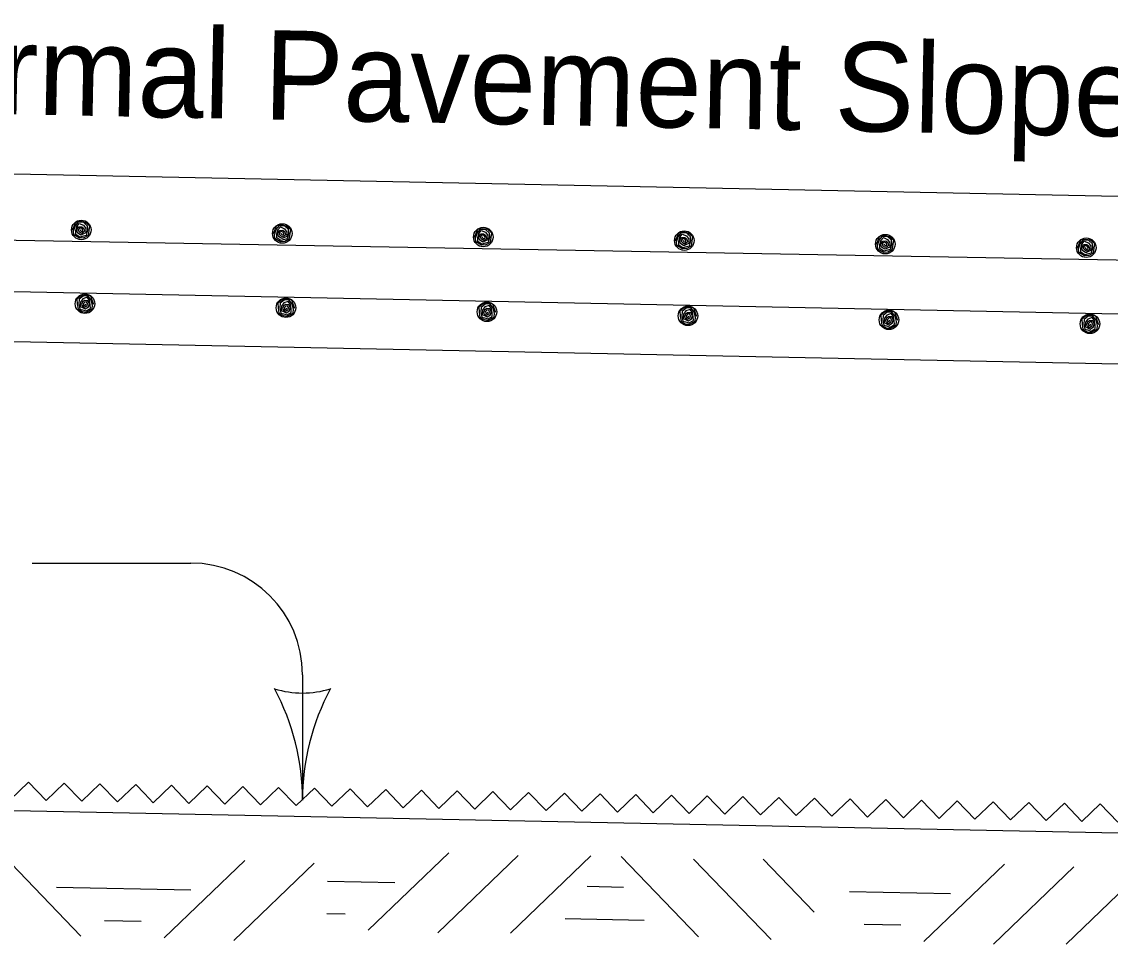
# Model space of a CAD drawing. Extents: x 10133 to 81668, y 7924 to 11018.
# Drawn here: x 10637.4 to 10832.4, y 8280 to 8445.3 of the extents above; entities that cross this region are included whole.
import ezdxf

# ---------------------------------------------------------------- set-up
doc = ezdxf.new("R2010")
doc.units = 0
doc.layers.add('BridgeExistingStructure', color=7, linetype='Continuous')
doc.layers.add('RasterAttachment', color=7, linetype='Continuous')

msp = doc.modelspace()

# ---------------------------------------------------------------- linework, layer by layer
at = {"layer": 'RasterAttachment'}
for p, q in [((10451.65, 8421.69), (11221.33, 8406.24)), ((10468, 8409.1), (11224.07, 8395.72)), ((10648.09, 8407.89), (10648.09, 8407.89)), ((10683.12, 8405.29), (10683.12, 8405.29)), ((10756.1, 8405.98), (10756.1, 8405.98)), ((10792.1, 8405.34), (10792.1, 8405.34)), ((10719.12, 8404.65), (10719.12, 8404.65)), ((10828.11, 8404.71), (10828.11, 8404.71)), ((11224.78, 8385.06), (10468.75, 8400.23)), ((10648.75, 8396.5), (10648.75, 8396.5)), ((10756.76, 8394.33), (10756.76, 8394.33)), ((10792.76, 8393.61), (10792.76, 8393.61)), ((10451.65, 8391.68), (11243.49, 8375.79)), ((10828.76, 8392.89), (10828.76, 8392.89)), ((10639.3, 8348.3), (10667.72, 8348.3)), ((10687.72, 8328.3), (10687.72, 8305.81)), ((10335.32, 8310), (11315.49, 8290.32)), ((10634.17, 8295.9), (10648.02, 8281.48)), ((10713.92, 8296.39), (10699.5, 8282.54)), ((10726.36, 8295.92), (10711.94, 8282.06)), ((10739.37, 8295.88), (10724.95, 8282.03)), ((10744.78, 8295.77), (10758.64, 8281.35)), ((10677.38, 8295.03), (10662.96, 8281.18)), ((10689.83, 8294.56), (10675.4, 8280.7)), ((10757.78, 8295.29), (10771.64, 8280.86)), ((10770.24, 8295.26), (10779.34, 8285.79)), ((10813.45, 8294.39), (10799.03, 8280.54)), ((10825.9, 8293.92), (10811.47, 8280.06)), ((10838.9, 8293.88), (10824.48, 8280.03))]:
    msp.add_line(p, q, dxfattribs=at)
for points in [[(10646.48, 8407.9), (10646.77, 8408.48), (10647.09, 8409.39), (10648.03, 8409.53), (10648.84, 8409.37), (10649.58, 8408.75), (10649.47, 8407.88), (10649.3, 8406.97), (10648.55, 8406.55), (10647.77, 8406.5), (10646.78, 8407.08), (10646.72, 8407.76), (10646.99, 8408.67), (10647.61, 8409.4), (10648.48, 8409.34), (10649.16, 8408.73), (10649.21, 8407.9), (10648.99, 8406.99), (10648.47, 8406.87), (10647.84, 8406.7), (10647.1, 8407.17), (10647.14, 8407.83), (10647.3, 8408.6), (10647.74, 8409.13), (10648.5, 8408.83), (10648.92, 8408.23), (10648.92, 8407.46), (10648.5, 8407.28), (10648.02, 8407.05), (10647.43, 8407.45), (10647.31, 8408.03), (10647.6, 8408.53), (10648.17, 8408.54), (10648.56, 8408.25), (10648.68, 8407.73), (10648.46, 8407.49), (10648.14, 8407.35), (10647.7, 8407.64), (10647.62, 8408.01), (10647.85, 8408.35), (10648.15, 8408.28), (10648.34, 8408.01), (10648.32, 8407.65), (10648.06, 8407.67), (10647.93, 8407.99)], [(10682.49, 8407.26), (10682.77, 8407.84), (10683.09, 8408.75), (10684.03, 8408.89), (10684.84, 8408.73), (10685.58, 8408.12), (10685.47, 8407.25), (10685.3, 8406.33), (10684.55, 8405.92), (10683.78, 8405.86), (10682.79, 8406.45), (10682.73, 8407.12), (10682.99, 8408.03), (10683.61, 8408.76), (10684.48, 8408.71), (10685.16, 8408.09), (10685.21, 8407.26), (10685, 8406.35), (10684.47, 8406.23), (10683.84, 8406.07), (10683.1, 8406.53), (10683.14, 8407.2), (10683.3, 8407.96), (10683.75, 8408.5), (10684.5, 8408.19), (10684.92, 8407.59), (10684.92, 8406.82), (10684.5, 8406.64), (10684.02, 8406.41), (10683.43, 8406.82), (10683.31, 8407.39), (10683.6, 8407.89), (10684.17, 8407.9), (10684.56, 8407.62), (10684.68, 8407.09), (10684.46, 8406.85), (10684.14, 8406.72), (10683.7, 8407), (10683.62, 8407.37), (10683.85, 8407.72), (10684.15, 8407.64), (10684.34, 8407.38), (10684.32, 8407.01), (10684.06, 8407.03), (10683.93, 8407.35)], [(10718.49, 8406.62), (10718.78, 8407.2), (10719.1, 8408.11), (10720.03, 8408.25), (10720.85, 8408.1), (10721.58, 8407.48), (10721.47, 8406.61), (10721.31, 8405.69), (10720.56, 8405.28), (10719.78, 8405.23), (10718.79, 8405.81), (10718.73, 8406.48), (10719, 8407.4), (10719.61, 8408.13), (10720.49, 8408.07), (10721.17, 8407.46), (10721.21, 8406.63), (10721, 8405.71), (10720.48, 8405.59), (10719.85, 8405.43), (10719.1, 8405.89), (10719.15, 8406.56), (10719.3, 8407.32), (10719.75, 8407.86), (10720.5, 8407.55), (10720.93, 8406.96), (10720.93, 8406.18), (10720.5, 8406.01), (10720.02, 8405.78), (10719.43, 8406.18), (10719.32, 8406.75), (10719.61, 8407.25), (10720.17, 8407.26), (10720.57, 8406.98), (10720.69, 8406.46), (10720.47, 8406.21), (10720.15, 8406.08), (10719.7, 8406.37), (10719.62, 8406.74), (10719.85, 8407.08), (10720.16, 8407.01), (10720.35, 8406.74), (10720.32, 8406.38), (10720.06, 8406.39), (10719.93, 8406.71)], [(10754.49, 8405.99), (10754.78, 8406.57), (10755.1, 8407.47), (10756.04, 8407.62), (10756.85, 8407.46), (10757.59, 8406.84), (10757.48, 8405.97), (10757.31, 8405.06), (10756.56, 8404.64), (10755.78, 8404.59), (10754.79, 8405.17), (10754.73, 8405.85), (10755, 8406.76), (10755.62, 8407.49), (10756.49, 8407.43), (10757.17, 8406.82), (10757.22, 8405.99), (10757, 8405.08), (10756.48, 8404.96), (10755.85, 8404.79), (10755.11, 8405.25), (10755.15, 8405.92), (10755.31, 8406.69), (10755.75, 8407.22), (10756.51, 8406.91), (10756.93, 8406.32), (10756.93, 8405.55), (10756.51, 8405.37), (10756.03, 8405.14), (10755.44, 8405.54), (10755.32, 8406.12), (10755.61, 8406.61), (10756.18, 8406.63), (10756.57, 8406.34), (10756.69, 8405.82), (10756.47, 8405.58), (10756.15, 8405.44), (10755.71, 8405.73), (10755.63, 8406.1), (10755.86, 8406.44), (10756.16, 8406.37), (10756.35, 8406.1), (10756.32, 8405.74), (10756.07, 8405.76), (10755.94, 8406.08)], [(10790.5, 8405.35), (10790.79, 8405.93), (10791.1, 8406.84), (10792.04, 8406.98), (10792.86, 8406.82), (10793.59, 8406.21), (10793.48, 8405.34), (10793.31, 8404.42), (10792.57, 8404.01), (10791.79, 8403.95), (10790.8, 8404.53), (10790.74, 8405.21), (10791.01, 8406.12), (10791.62, 8406.85), (10792.49, 8406.79), (10793.17, 8406.18), (10793.22, 8405.35), (10793.01, 8404.44), (10792.48, 8404.32), (10791.85, 8404.16), (10791.11, 8404.62), (10791.16, 8405.29), (10791.31, 8406.05), (10791.76, 8406.59), (10792.51, 8406.28), (10792.93, 8405.68), (10792.93, 8404.91), (10792.51, 8404.73), (10792.03, 8404.5), (10791.44, 8404.9), (10791.32, 8405.48), (10791.61, 8405.98), (10792.18, 8405.99), (10792.58, 8405.71), (10792.7, 8405.18), (10792.47, 8404.94), (10792.15, 8404.81), (10791.71, 8405.09), (10791.63, 8405.46), (10791.86, 8405.81), (10792.17, 8405.73), (10792.35, 8405.46), (10792.33, 8405.1), (10792.07, 8405.12), (10791.94, 8405.44)], [(10826.5, 8404.71), (10826.79, 8405.29), (10827.11, 8406.2), (10828.04, 8406.34), (10828.86, 8406.18), (10829.59, 8405.57), (10829.48, 8404.7), (10829.32, 8403.78), (10828.57, 8403.37), (10827.79, 8403.32), (10826.8, 8403.9), (10826.74, 8404.57), (10827.01, 8405.48), (10827.62, 8406.22), (10828.5, 8406.16), (10829.18, 8405.54), (10829.22, 8404.72), (10829.01, 8403.8), (10828.49, 8403.68), (10827.86, 8403.52), (10827.11, 8403.98), (10827.16, 8404.65), (10827.31, 8405.41), (10827.76, 8405.95), (10828.51, 8405.64), (10828.94, 8405.05), (10828.94, 8404.27), (10828.51, 8404.09), (10828.03, 8403.87), (10827.44, 8404.27), (10827.33, 8404.84), (10827.62, 8405.34), (10828.18, 8405.35), (10828.58, 8405.07), (10828.7, 8404.55), (10828.48, 8404.3), (10828.16, 8404.17), (10827.71, 8404.46), (10827.63, 8404.82), (10827.86, 8405.17), (10828.17, 8405.1), (10828.36, 8404.83), (10828.33, 8404.47), (10828.07, 8404.48), (10827.94, 8404.8)], [(10650.36, 8394.61), (10650.09, 8395.21), (10649.81, 8396.12), (10648.88, 8396.3), (10648.06, 8396.18), (10647.3, 8395.59), (10647.38, 8394.71), (10647.51, 8393.79), (10648.24, 8393.35), (10649.02, 8393.27), (10650.03, 8393.81), (10650.12, 8394.48), (10649.88, 8395.41), (10649.29, 8396.16), (10648.42, 8396.13), (10647.72, 8395.55), (10647.64, 8394.72), (10647.82, 8393.8), (10648.34, 8393.66), (10648.96, 8393.47), (10649.72, 8393.91), (10649.7, 8394.58), (10649.58, 8395.34), (10649.15, 8395.9), (10648.38, 8395.62), (10647.94, 8395.04), (10647.91, 8394.27), (10648.33, 8394.07), (10648.8, 8393.83), (10649.4, 8394.21), (10649.54, 8394.78), (10649.27, 8395.28), (10648.7, 8395.32), (10648.3, 8395.05), (10648.16, 8394.53), (10648.37, 8394.28), (10648.68, 8394.13), (10649.14, 8394.4), (10649.23, 8394.77), (10649.02, 8395.12), (10648.71, 8395.06), (10648.51, 8394.8), (10648.52, 8394.44), (10648.78, 8394.45), (10648.92, 8394.76)], [(10686.36, 8393.89), (10686.1, 8394.48), (10685.81, 8395.4), (10684.88, 8395.58), (10684.06, 8395.45), (10683.31, 8394.87), (10683.38, 8393.99), (10683.51, 8393.07), (10684.25, 8392.63), (10685.02, 8392.55), (10686.03, 8393.09), (10686.12, 8393.76), (10685.88, 8394.68), (10685.3, 8395.44), (10684.42, 8395.41), (10683.72, 8394.83), (10683.64, 8394), (10683.82, 8393.08), (10684.34, 8392.94), (10684.96, 8392.75), (10685.72, 8393.18), (10685.7, 8393.85), (10685.58, 8394.62), (10685.15, 8395.18), (10684.39, 8394.9), (10683.94, 8394.32), (10683.91, 8393.54), (10684.33, 8393.35), (10684.8, 8393.11), (10685.4, 8393.48), (10685.54, 8394.06), (10685.27, 8394.56), (10684.7, 8394.6), (10684.3, 8394.33), (10684.16, 8393.81), (10684.37, 8393.56), (10684.69, 8393.41), (10685.14, 8393.68), (10685.23, 8394.05), (10685.02, 8394.4), (10684.71, 8394.34), (10684.51, 8394.08), (10684.52, 8393.72), (10684.78, 8393.72), (10684.93, 8394.04)], [(10722.36, 8393.17), (10722.1, 8393.76), (10721.81, 8394.68), (10720.88, 8394.86), (10720.06, 8394.73), (10719.31, 8394.14), (10719.38, 8393.27), (10719.51, 8392.35), (10720.25, 8391.9), (10721.02, 8391.82), (10722.04, 8392.37), (10722.12, 8393.04), (10721.89, 8393.96), (10721.3, 8394.72), (10720.42, 8394.69), (10719.72, 8394.1), (10719.64, 8393.28), (10719.82, 8392.36), (10720.34, 8392.22), (10720.96, 8392.03), (10721.72, 8392.46), (10721.7, 8393.13), (10721.58, 8393.9), (10721.15, 8394.45), (10720.39, 8394.17), (10719.94, 8393.59), (10719.91, 8392.82), (10720.33, 8392.63), (10720.8, 8392.38), (10721.41, 8392.76), (10721.54, 8393.33), (10721.27, 8393.84), (10720.71, 8393.87), (10720.3, 8393.61), (10720.16, 8393.09), (10720.38, 8392.83), (10720.69, 8392.69), (10721.14, 8392.96), (10721.24, 8393.32), (10721.02, 8393.68), (10720.71, 8393.62), (10720.51, 8393.35), (10720.53, 8392.99), (10720.78, 8393), (10720.93, 8393.31)], [(10758.37, 8392.45), (10758.1, 8393.04), (10757.82, 8393.96), (10756.88, 8394.13), (10756.06, 8394.01), (10755.31, 8393.42), (10755.39, 8392.55), (10755.52, 8391.62), (10756.25, 8391.18), (10757.02, 8391.1), (10758.04, 8391.64), (10758.12, 8392.32), (10757.89, 8393.24), (10757.3, 8393.99), (10756.43, 8393.97), (10755.72, 8393.38), (10755.64, 8392.55), (10755.82, 8391.63), (10756.34, 8391.49), (10756.97, 8391.31), (10757.73, 8391.74), (10757.71, 8392.41), (10757.58, 8393.18), (10757.15, 8393.73), (10756.39, 8393.45), (10755.94, 8392.87), (10755.91, 8392.1), (10756.33, 8391.9), (10756.8, 8391.66), (10757.41, 8392.04), (10757.55, 8392.61), (10757.27, 8393.12), (10756.71, 8393.15), (10756.3, 8392.88), (10756.16, 8392.36), (10756.38, 8392.11), (10756.69, 8391.97), (10757.14, 8392.24), (10757.24, 8392.6), (10757.02, 8392.95), (10756.71, 8392.89), (10756.52, 8392.63), (10756.53, 8392.27), (10756.78, 8392.28), (10756.93, 8392.59)], [(10794.37, 8391.72), (10794.1, 8392.32), (10793.82, 8393.23), (10792.89, 8393.41), (10792.07, 8393.29), (10791.31, 8392.7), (10791.39, 8391.82), (10791.52, 8390.9), (10792.25, 8390.46), (10793.03, 8390.38), (10794.04, 8390.92), (10794.12, 8391.59), (10793.89, 8392.52), (10793.3, 8393.27), (10792.43, 8393.24), (10791.72, 8392.66), (10791.65, 8391.83), (10791.83, 8390.91), (10792.34, 8390.77), (10792.97, 8390.58), (10793.73, 8391.02), (10793.71, 8391.69), (10793.58, 8392.45), (10793.15, 8393.01), (10792.39, 8392.73), (10791.94, 8392.15), (10791.92, 8391.38), (10792.33, 8391.18), (10792.8, 8390.94), (10793.41, 8391.32), (10793.55, 8391.89), (10793.28, 8392.39), (10792.71, 8392.43), (10792.3, 8392.16), (10792.16, 8391.64), (10792.38, 8391.39), (10792.69, 8391.24), (10793.15, 8391.51), (10793.24, 8391.88), (10793.02, 8392.23), (10792.72, 8392.17), (10792.52, 8391.91), (10792.53, 8391.55), (10792.79, 8391.56), (10792.93, 8391.87)], [(10830.37, 8391), (10830.1, 8391.59), (10829.82, 8392.51), (10828.89, 8392.69), (10828.07, 8392.56), (10827.31, 8391.97), (10827.39, 8391.1), (10827.52, 8390.18), (10828.25, 8389.74), (10829.03, 8389.66), (10830.04, 8390.2), (10830.12, 8390.87), (10829.89, 8391.79), (10829.3, 8392.55), (10828.43, 8392.52), (10827.73, 8391.93), (10827.65, 8391.11), (10827.83, 8390.19), (10828.35, 8390.05), (10828.97, 8389.86), (10829.73, 8390.29), (10829.71, 8390.96), (10829.58, 8391.73), (10829.16, 8392.29), (10828.39, 8392.01), (10827.95, 8391.43), (10827.92, 8390.65), (10828.33, 8390.46), (10828.8, 8390.22), (10829.41, 8390.59), (10829.55, 8391.16), (10829.28, 8391.67), (10828.71, 8391.71), (10828.31, 8391.44), (10828.17, 8390.92), (10828.38, 8390.67), (10828.69, 8390.52), (10829.15, 8390.79), (10829.24, 8391.16), (10829.02, 8391.51), (10828.72, 8391.45), (10828.52, 8391.19), (10828.53, 8390.83), (10828.79, 8390.83), (10828.93, 8391.15)], [(10635.38, 8305.89), (10638.65, 8309.03), (10641.78, 8305.77), (10645.05, 8308.9), (10648.18, 8305.64), (10651.44, 8308.77), (10654.58, 8305.51), (10657.84, 8308.64), (10659.41, 8307.01)], [(10659.41, 8307.01), (10660.98, 8305.38), (10664.24, 8308.52), (10667.38, 8305.25), (10670.64, 8308.39), (10673.78, 8305.12), (10677.04, 8308.26), (10680.17, 8305), (10683.44, 8308.13), (10686.57, 8304.87), (10689.84, 8308), (10692.97, 8304.74), (10696.24, 8307.87), (10699.37, 8304.61), (10702.63, 8307.74), (10705.77, 8304.48), (10709.03, 8307.62), (10712.17, 8304.35), (10715.43, 8307.49), (10718.57, 8304.22), (10721.83, 8307.36), (10724.97, 8304.1), (10728.23, 8307.23), (10731.36, 8303.97), (10734.63, 8307.1), (10736.2, 8305.47)], [(10736.2, 8305.47), (10737.76, 8303.84), (10741.03, 8306.97), (10744.16, 8303.71), (10747.43, 8306.85), (10750.56, 8303.58), (10753.82, 8306.72), (10756.96, 8303.45), (10760.22, 8306.59), (10763.36, 8303.33), (10766.62, 8306.46), (10769.76, 8303.2), (10773.02, 8306.33), (10776.16, 8303.07), (10779.42, 8306.2), (10782.55, 8302.94), (10785.82, 8306.08), (10788.95, 8302.81), (10792.22, 8305.95), (10795.35, 8302.68), (10798.61, 8305.82), (10801.75, 8302.56), (10805.01, 8305.69), (10808.15, 8302.43), (10811.41, 8305.56), (10812.98, 8303.93)], [(10812.98, 8303.93), (10814.55, 8302.3), (10817.81, 8305.43), (10820.95, 8302.17), (10824.21, 8305.31), (10827.34, 8302.04), (10830.61, 8305.18), (10833.74, 8301.91)], [(10643.64, 8290.23), (10667.69, 8289.75)], [(10692.2, 8291.35), (10704.23, 8291.11)], [(10738.7, 8290.4), (10745.23, 8290.26)], [(10785.7, 8289.48), (10803.76, 8289.11)], [(10652.28, 8284.26), (10658.81, 8284.13)], [(10692.08, 8285.55), (10695.35, 8285.49)], [(10734.76, 8284.62), (10748.94, 8284.33)], [(10788.35, 8283.62), (10794.88, 8283.49)]]:
    msp.add_lwpolyline(points, dxfattribs=at)
for centre in [(10648.09, 8407.97), (10684.1, 8407.34), (10720.1, 8406.7), (10756.1, 8406.06), (10792.11, 8405.43), (10828.11, 8404.79), (10648.75, 8394.75), (10684.76, 8394.03), (10720.76, 8393.31), (10756.76, 8392.58), (10792.76, 8391.86), (10828.76, 8391.14)]:
    msp.add_circle(centre, 1.75, dxfattribs=at)
for centre, radius, start, end in [((10667.72, 8328.3), 20, 0, 90), ((10687.72, 8341.44), 16.42, 252.2666, 287.7333), ((10645.22, 8305.81), 42.5, 360, 28.0725), ((10730.22, 8305.81), 42.5, 151.9275, 180)]:
    msp.add_arc(centre, radius, start, end, dxfattribs=at)

# ---------------------------------------------------------------- texts
at = {"layer": 'BridgeExistingStructure'}
msp.add_text('Normal Pavement Slope', height=16, rotation=358.8502, dxfattribs=at).set_placement((10605.77, 8429.29))

doc.saveas('drawing.dxf')
